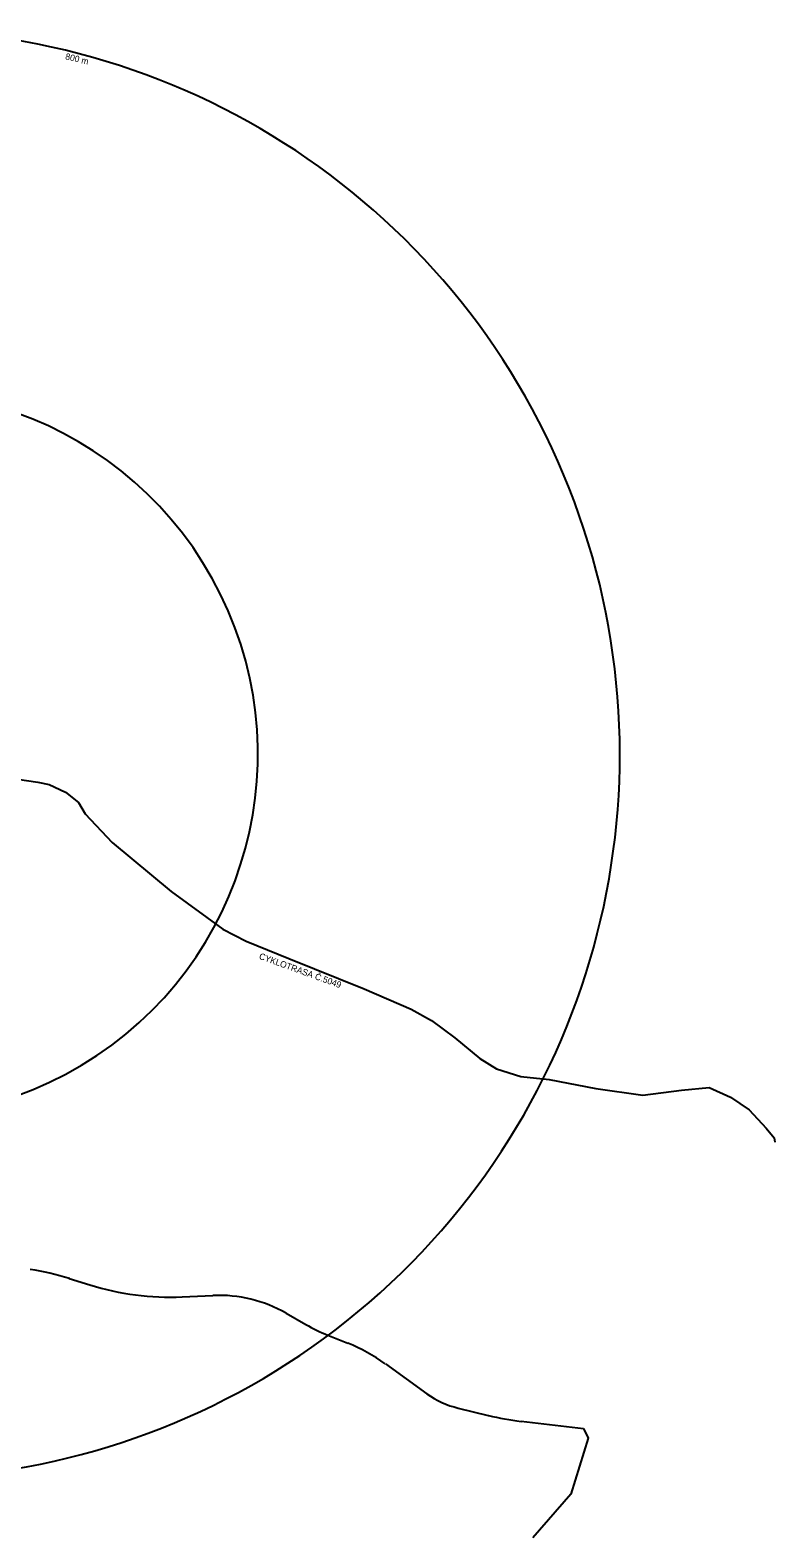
# Model space of a CAD drawing. Extents: x -520790 to -517278, y -1190021 to -1185077.
# Drawn here: x -518101 to -517278, y -1188181 to -1186516 of the extents above; entities that cross this region are included whole.
import ezdxf

# ---------------------------------------------------------------- set-up
doc = ezdxf.new("R2010")
doc.units = 0
doc.layers.add('cyklostezka_s', color=7, linetype='Continuous')
doc.layers.add('dostupnost_s', color=7, linetype='Continuous')

msp = doc.modelspace()

# ---------------------------------------------------------------- linework, layer by layer
at = {"layer": 'cyklostezka_s'}
for p, q in [((-518058.1, -1187894.8), (-518035.3, -1187901.8)), ((-517933.5, -1187915), (-517899.4, -1187913.6)), ((-517818.6, -1187933.2), (-517796.8, -1187945.6)), ((-517772.6, -1187957.3), (-517750.4, -1187966.3)), ((-517708.9, -1187989.1), (-517663, -1188022.1)), ((-517628.4, -1188037.9), (-517595.1, -1188046)), ((-517558.9, -1188052.5), (-517489.9, -1188060.5))]:
    msp.add_line(p, q, dxfattribs=at)
for points in [[(-518145.5, -1187338.9), (-518093, -1187346.5), (-518080.5, -1187349.2), (-518062.4, -1187357.5), (-518048.1, -1187369), (-518040.6, -1187381.4), (-518010.7, -1187413), (-517945.5, -1187467.4), (-517888.3, -1187509), (-517862.8, -1187522.2), (-517815.5, -1187541.1), (-517732.4, -1187574.7), (-517680.3, -1187597.2), (-517657.9, -1187609.9), (-517632.2, -1187628.8), (-517604.6, -1187651.9), (-517586, -1187663), (-517559, -1187671.7), (-517527.9, -1187675), (-517476.2, -1187684.9), (-517424.5, -1187692.1), (-517381.6, -1187686.9), (-517351.1, -1187683.8), (-517327.5, -1187694.3), (-517306.8, -1187708.3), (-517288.1, -1187728.6), (-517279.1, -1187739.4), (-517278.5, -1187744.1)], [(-517489.9, -1188060.5), (-517484.9, -1188071.1), (-517504, -1188132.9), (-517546, -1188181.3)]]:
    msp.add_lwpolyline(points, dxfattribs=at)
for centre, radius, start, end in [((-518147, -1188181.3), 300, 72.7538, 81.2533), ((-517946.4, -1187615.3), 300, 252.7538, 272.4553), ((-517892.9, -1188063.4), 150, 60.2686, 92.4562), ((-517697.6, -1187771.9), 200, 240.2676, 247.9824), ((-517825.4, -1188151.7), 200, 54.3846, 67.9824), ((-517604.7, -1187940.8), 100, 234.3839, 256.3001), ((-517524, -1187754.6), 300, 256.2985, 263.316)]:
    msp.add_arc(centre, radius, start, end, dxfattribs=at)
at = {"layer": 'dostupnost_s'}
for radius, start, end in [(800, 238.9173, 94.6412), (400, 212.6563, 117.2847)]:
    msp.add_arc((-518249.8, -1187315.8), radius, start, end, dxfattribs=at)

# ---------------------------------------------------------------- texts
at = {"layer": 'cyklostezka_s'}
msp.add_text('CYKLOTRASA Č.5049', height=7, rotation=340.0691, dxfattribs=at).set_placement((-517849.1, -1187541.5))
at = {"layer": 'dostupnost_s'}
msp.add_text('800 m', height=7, rotation=346.4234, dxfattribs=at).set_placement((-518063, -1186547.8))

doc.saveas('drawing.dxf')
